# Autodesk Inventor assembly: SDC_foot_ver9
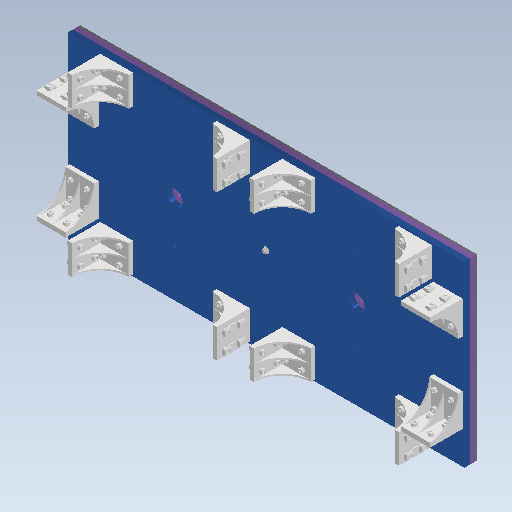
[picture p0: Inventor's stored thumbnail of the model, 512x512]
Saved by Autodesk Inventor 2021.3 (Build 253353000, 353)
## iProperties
Created: 2022-02
Part Number: SDC_foot_ver9
Document SubType Name: Assembly
Designer: kengo
Author: kengo
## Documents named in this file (6)
- C:\Users\kengo\Documents\frame_misumi_ver12\Anker\foot\SDC_foot_ver9.iam
- C:\Users\kengo\Documents\frame_misumi_ver12\Anker\foot\SDC_Anker_down_plate_ver9.ipt
- C:\Users\kengo\Documents\frame_misumi_ver12\Anker\foot\SDC_Anker_plate_ver9.ipt
- C:\Users\kengo\Documents\frame_misumi_ver12\Anker\foot\SDC_Anker_PVC_plate_ver9.ipt
- C:\Users\kengo\Documents\frame_misumi_ver12\Anker\foot\HBLFSDW8-90-SET_foot.iam
- C:\Users\kengo\Documents\frame_misumi_ver12\Anker\foot\SJPNGB10-P17-B15-G8.ipt
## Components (16 placed, 5 different names)
1. SDC_Anker_down_plate_ver9:1 — メイト:1, フラッシュ:1, フラッシュ:2, メイト:2, フラッシュ:3, フラッシュ:4, フラッシュ:7, フラッシュ:11, フラッシュ:14, フラッシュ:22, 回転:1
2. SDC_Anker_plate_ver9:1 — メイト:1, フラッシュ:1, フラッシュ:2, メイト:3, フラッシュ:5, フラッシュ:6, メイト:4, フラッシュ:8, メイト:5, フラッシュ:9, メイト:7, フラッシュ:10, メイト:8, フラッシュ:12, フラッシュ:13, メイト:9, フラッシュ:15, メイト:10, フラッシュ:16, メイト:12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
3. SDC_Anker_PVC_plate_ver9:1 — メイト:2, フラッシュ:3, フラッシュ:4
4. HBLFSDW8-90-SET_foot:1 [sub-assembly] — メイト:4, フラッシュ:7, フラッシュ:8
5. HBLFSDW8-90-SET_foot:2 [sub-assembly] — メイト:5, フラッシュ:9, メイト:6
6. HBLFSDW8-90-SET_foot:3 [sub-assembly] — メイト:7, フラッシュ:10, フラッシュ:11, メイト:11
7. HBLFSDW8-90-SET_foot:4 [sub-assembly] — メイト:8, フラッシュ:12, フラッシュ:13
8. HBLFSDW8-90-SET_foot:5 [sub-assembly] — メイト:3, フラッシュ:5, フラッシュ:6, メイト:6
9. HBLFSDW8-90-SET_foot:6 [sub-assembly] — メイト:9, フラッシュ:14, フラッシュ:15
10. HBLFSDW8-90-SET_foot:7 [sub-assembly] — メイト:13, メイト:14, フラッシュ:19, メイト:16
11. HBLFSDW8-90-SET_foot:8 [sub-assembly] — メイト:15, フラッシュ:20, メイト:16
12. HBLFSDW8-90-SET_foot:9 [sub-assembly] — メイト:10, フラッシュ:16, メイト:11
13. HBLFSDW8-90-SET_foot:10 [sub-assembly] — メイト:12, フラッシュ:17, フラッシュ:18, メイト:14
14. HBLFSDW8-90-SET_foot:11 [sub-assembly] — メイト:17, フラッシュ:21, フラッシュ:22
15. HBLFSDW8-90-SET_foot:12 [sub-assembly] — メイト:18, フラッシュ:23, フラッシュ:24
16. SJPNGB10-P17-B15-G8:1 — 回転:1
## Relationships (43: Flush 24, Mate 18, RevoluteJoint 1)
- メイト:1 [Mate]: SDC_Anker_down_plate_ver9:1 ↔ SDC_Anker_plate_ver9:1
- フラッシュ:1 [Flush]: SDC_Anker_down_plate_ver9:1 ↔ SDC_Anker_plate_ver9:1
- フラッシュ:2 [Flush]: SDC_Anker_down_plate_ver9:1 ↔ SDC_Anker_plate_ver9:1
- メイト:2 [Mate]: SDC_Anker_down_plate_ver9:1 ↔ SDC_Anker_PVC_plate_ver9:1
- フラッシュ:3 [Flush]: SDC_Anker_down_plate_ver9:1 ↔ SDC_Anker_PVC_plate_ver9:1
- フラッシュ:4 [Flush]: SDC_Anker_down_plate_ver9:1 ↔ SDC_Anker_PVC_plate_ver9:1
- メイト:3 [Mate]: SDC_Anker_plate_ver9:1 ↔ HBLFSDW8-90-SET_foot:5
- フラッシュ:5 [Flush]: SDC_Anker_plate_ver9:1 ↔ HBLFSDW8-90-SET_foot:5
- フラッシュ:6 [Flush]: SDC_Anker_plate_ver9:1 ↔ HBLFSDW8-90-SET_foot:5
- メイト:4 [Mate]: SDC_Anker_plate_ver9:1 ↔ HBLFSDW8-90-SET_foot:1
- フラッシュ:7 [Flush]: SDC_Anker_down_plate_ver9:1 ↔ HBLFSDW8-90-SET_foot:1
- フラッシュ:8 [Flush]: SDC_Anker_plate_ver9:1 ↔ HBLFSDW8-90-SET_foot:1
- メイト:5 [Mate]: SDC_Anker_plate_ver9:1 ↔ HBLFSDW8-90-SET_foot:2
- フラッシュ:9 [Flush]: SDC_Anker_plate_ver9:1 ↔ HBLFSDW8-90-SET_foot:2
- メイト:6 [Mate]: HBLFSDW8-90-SET_foot:2 ↔ HBLFSDW8-90-SET_foot:5
- メイト:7 [Mate]: SDC_Anker_plate_ver9:1 ↔ HBLFSDW8-90-SET_foot:3
- フラッシュ:10 [Flush]: SDC_Anker_plate_ver9:1 ↔ HBLFSDW8-90-SET_foot:3
- フラッシュ:11 [Flush]: SDC_Anker_down_plate_ver9:1 ↔ HBLFSDW8-90-SET_foot:3
- メイト:8 [Mate]: SDC_Anker_plate_ver9:1 ↔ HBLFSDW8-90-SET_foot:4
- フラッシュ:12 [Flush]: SDC_Anker_plate_ver9:1 ↔ HBLFSDW8-90-SET_foot:4
- フラッシュ:13 [Flush]: SDC_Anker_plate_ver9:1 ↔ HBLFSDW8-90-SET_foot:4
- メイト:9 [Mate]: SDC_Anker_plate_ver9:1 ↔ HBLFSDW8-90-SET_foot:6
- フラッシュ:14 [Flush]: SDC_Anker_down_plate_ver9:1 ↔ HBLFSDW8-90-SET_foot:6
- フラッシュ:15 [Flush]: SDC_Anker_plate_ver9:1 ↔ HBLFSDW8-90-SET_foot:6
- メイト:10 [Mate]: SDC_Anker_plate_ver9:1 ↔ HBLFSDW8-90-SET_foot:9
- フラッシュ:16 [Flush]: SDC_Anker_plate_ver9:1 ↔ HBLFSDW8-90-SET_foot:9
- メイト:11 [Mate]: HBLFSDW8-90-SET_foot:3 ↔ HBLFSDW8-90-SET_foot:9
- メイト:12 [Mate]: SDC_Anker_plate_ver9:1 ↔ HBLFSDW8-90-SET_foot:10
- フラッシュ:17 [Flush]: SDC_Anker_plate_ver9:1 ↔ HBLFSDW8-90-SET_foot:10
- フラッシュ:18 [Flush]: SDC_Anker_plate_ver9:1 ↔ HBLFSDW8-90-SET_foot:10
- メイト:13 [Mate]: SDC_Anker_plate_ver9:1 ↔ HBLFSDW8-90-SET_foot:7
- メイト:14 [Mate]: HBLFSDW8-90-SET_foot:7 ↔ HBLFSDW8-90-SET_foot:10
- フラッシュ:19 [Flush]: SDC_Anker_plate_ver9:1 ↔ HBLFSDW8-90-SET_foot:7
- メイト:15 [Mate]: SDC_Anker_plate_ver9:1 ↔ HBLFSDW8-90-SET_foot:8
- フラッシュ:20 [Flush]: SDC_Anker_plate_ver9:1 ↔ HBLFSDW8-90-SET_foot:8
- メイト:16 [Mate]: HBLFSDW8-90-SET_foot:7 ↔ HBLFSDW8-90-SET_foot:8
- メイト:17 [Mate]: SDC_Anker_plate_ver9:1 ↔ HBLFSDW8-90-SET_foot:11
- フラッシュ:21 [Flush]: SDC_Anker_plate_ver9:1 ↔ HBLFSDW8-90-SET_foot:11
- フラッシュ:22 [Flush]: SDC_Anker_down_plate_ver9:1 ↔ HBLFSDW8-90-SET_foot:11
- メイト:18 [Mate]: SDC_Anker_plate_ver9:1 ↔ HBLFSDW8-90-SET_foot:12
- フラッシュ:23 [Flush]: SDC_Anker_plate_ver9:1 ↔ HBLFSDW8-90-SET_foot:12
- フラッシュ:24 [Flush]: SDC_Anker_plate_ver9:1 ↔ HBLFSDW8-90-SET_foot:12
- 回転:1 [RevoluteJoint]: SDC_Anker_down_plate_ver9:1 ↔ SJPNGB10-P17-B15-G8:1
